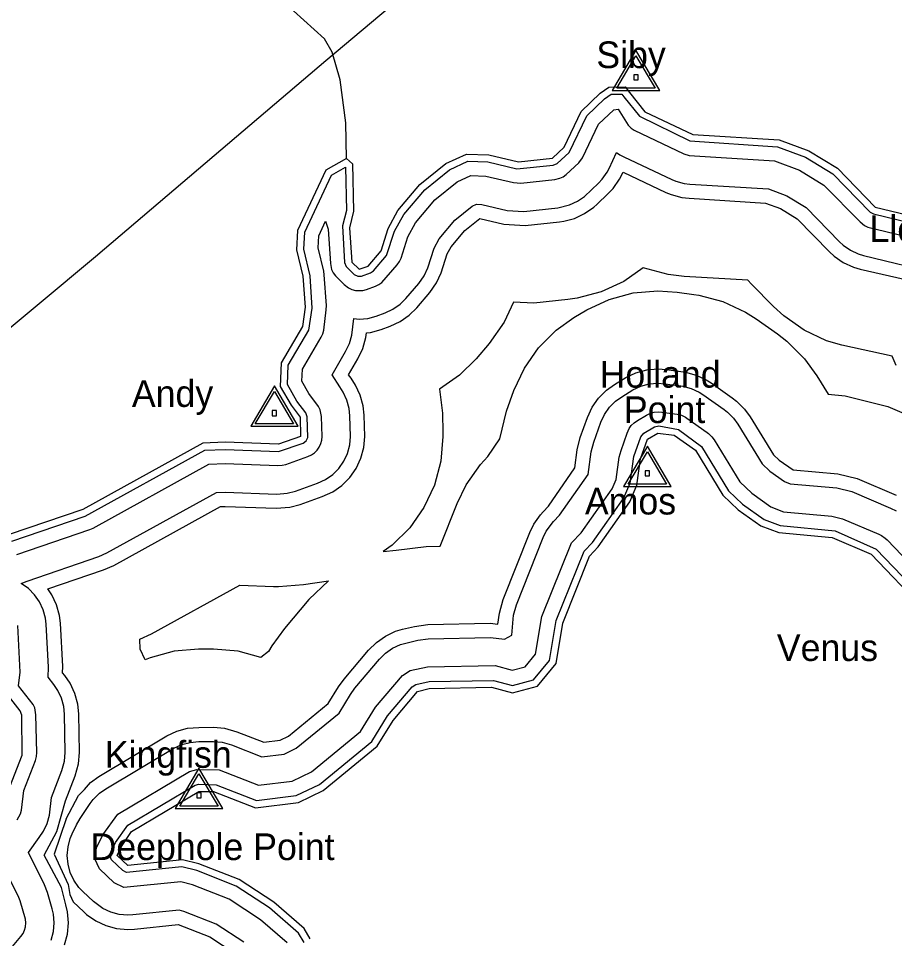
# Model space of a CAD drawing. Extents: x 2532689 to 2764727, y 536648 to 732970.
# Drawn here: x 2659104 to 2664029, y 576983 to 582158 of the extents above; entities that cross this region are included whole.
import ezdxf

# ---------------------------------------------------------------- set-up
doc = ezdxf.new("R2010")
doc.units = 0
for name, color, linetype in [('Exist Hydrographic Buffer Line', 7, 'Continuous'), ('Exist Hydrographic Creek Double Shore', 7, 'Continuous'), ('Exist Hydrographic Creek Single Shore', 7, 'Continuous'), ('Exist Hydrographic Point Label', 7, 'Continuous'), ('Exist Railroad Mainline', 7, 'Continuous'), ('Exist Survey Geodetic Marker CELL', 7, 'Continuous'), ('Exist Survey Geodetic Marker Label', 7, 'Continuous')]:
    doc.layers.add(name, color=color, linetype=linetype)

msp = doc.modelspace()

# ---------------------------------------------------------------- linework, layer by layer
at = {"layer": 'Exist Hydrographic Buffer Line'}
for points in [[(2661033.1, 580709.3), (2661083.1, 580727.7), (2661099.5, 580739.2), (2661172.5, 580824.2), (2661218.2, 580960.8), (2661270.5, 581054.6), (2661387.6, 581194.8), (2661527.4, 581306.8), (2661630.4, 581354.7), (2661741.7, 581350.4), (2661905.2, 581312.1), (2662110.6, 581332.1), (2662132.1, 581341.2), (2662198.8, 581404.6), (2662299.3, 581610.8), (2662398.9, 581706.4), (2662435, 581732.2), (2662494.9, 581732.5), (2662507.8, 581716), (2662594.1, 581607.7), (2662878.3, 581469.3), (2663370.9, 581436.3), (2663529, 581377.6), (2663682.1, 581283.6), (2663891.9, 581069.2), (2663911, 581058.3), (2664359, 580949.8)], [(2660699.9, 580185.2), (2660804.8, 580364.7), (2660814.1, 580384.3), (2660819.6, 580404.5), (2660834.4, 580519), (2660835, 580542.5), (2660823.1, 580716.1), (2660820, 580735.8), (2660788, 580868.3), (2660791.7, 580936), (2660830.3, 581018.1), (2660844.6, 580972.9), (2660857.5, 580779.7), (2660864.5, 580746.7), (2660873.3, 580727.8), (2660885.2, 580710.7), (2660935.5, 580660.9), (2660959.2, 580642.9), (2660978.3, 580634.1), (2660998.6, 580628.7), (2661019.3, 580626.9), (2661040, 580628.7), (2661060.3, 580634.1), (2661110.8, 580652.6), (2661129.2, 580661.3), (2661146.5, 580673.3), (2661233.2, 580772.2), (2661246.3, 580790.3), (2661255.1, 580809.3), (2661292.2, 580929.3), (2661336.7, 581009.2), (2661443.8, 581137.3), (2661570.1, 581238.3), (2661646.6, 581274), (2661731.1, 581270.8), (2661886.9, 581234.2), (2661927.3, 581231.7), (2662119.2, 581252.5), (2662147.3, 581259.1), (2662166.4, 581267.9), (2662183.6, 581279.9), (2662254.1, 581346.6), (2662275.3, 581373.6), (2662365.3, 581563.2), (2662450, 581644.5), (2662474.8, 581647.6), (2662531.4, 581557.9), (2662548, 581540.6), (2662565.4, 581528.6), (2662844.3, 581396.9), (2662874.6, 581387.3), (2663354, 581357.2), (2663493.7, 581305.3), (2663631.9, 581220.5), (2663834.7, 581013.3), (2663860.3, 580993.2), (2663879.4, 580984.4), (2664329.7, 580874.5)], [(2660966, 579759), (2660970.3, 579807.6), (2660967.2, 579923.7), (2660963.1, 579964.5), (2660950.2, 580011.7), (2660929.7, 580055.9), (2660910, 580085.7), (2660866.6, 580153.1), (2660943, 580284), (2660964.4, 580329.6), (2660977.1, 580376.8), (2660989.4, 580469.5), (2661019.3, 580466.9), (2661067.7, 580471.1), (2661115.1, 580483.7), (2661165.7, 580502.4), (2661209.2, 580522.7), (2661249.4, 580550.7), (2661281.8, 580582.9), (2661354.8, 580667.9), (2661384.7, 580710.3), (2661405.2, 580754.6), (2661440.3, 580866.1), (2661469.2, 580918.2), (2661556.4, 581022.5), (2661654.8, 581101.4), (2661679, 581112.6), (2661709.5, 581111.5), (2661850.4, 581078.4), (2661944.5, 581072.6), (2662136.7, 581093.5), (2662202.1, 581108.7), (2662246.4, 581129.3), (2662286.3, 581157.3), (2662364.1, 581230.6), (2662385.8, 581253.6), (2662413.9, 581293.6), (2662424.3, 581313.9), (2662466.6, 581403.2), (2662485.2, 581390.1), (2662506.2, 581379.2), (2662776, 581252.1), (2662799.6, 581242.4), (2662846.7, 581229.8), (2662878.1, 581226), (2663320.6, 581198.9), (2663423.4, 581160.7), (2663531.4, 581094.5), (2663720.1, 580901.5), (2663740.4, 580882.7), (2663780.4, 580854.7), (2663824.6, 580834.1), (2663854.4, 580825), (2664271.7, 580724)], [(2659066.4, 579218.2), (2659478.4, 579359.2), (2660151.3, 579729.5), (2660265.3, 579734.1), (2660564.7, 579723.2), (2660703.8, 579769.9), (2660721, 579781.9), (2660729.8, 579800.7), (2660727.3, 579917), (2660719.1, 579940.1), (2660669.5, 580005), (2660615.8, 580098.5), (2660620.7, 580208.5), (2660735.7, 580405.2), (2660755, 580529.2), (2660743.3, 580710.5), (2660707.4, 580861), (2660712.8, 580956), (2660863.3, 581275.6), (2660941.8, 581321.5), (2660947.4, 581078.3), (2660925.6, 580990.6), (2660937.3, 580785.1), (2660946.5, 580762.1), (2660991.2, 580718.2), (2661012.4, 580707.5), (2661033.1, 580709.3)], [(2659292, 578917.1), (2659269.4, 578949.3), (2659582.1, 579056.4), (2659639.1, 579081.6), (2660239.7, 579412.8), (2660266, 579413.8), (2660553.2, 579403.5), (2660628.7, 579408.7), (2660687.6, 579424.3), (2660811.6, 579468.7), (2660870.3, 579495.8), (2660921.7, 579531.8), (2660966, 579576.2), (2661002.1, 579627.6), (2661028.6, 579684.5), (2661044.8, 579745.1), (2661050.3, 579807.6), (2661047, 579925.8), (2661041.9, 579978.4), (2661025.5, 580039), (2660999, 580095.9), (2660973.6, 580134.2), (2660959, 580153.1), (2661012.1, 580243.6), (2661039.6, 580302.2), (2661055.8, 580362.9), (2661059.7, 580390.4), (2661081.9, 580392.4), (2661142.6, 580408.5), (2661193.6, 580427.3), (2661249.4, 580453.5), (2661300.9, 580489.5), (2661342.5, 580530.8), (2661415.5, 580615.9), (2661454, 580670.3), (2661480.5, 580727.2), (2661514.3, 580834.6), (2661535.6, 580872.8), (2661612.5, 580965), (2661697, 581032.2), (2661832.2, 581000.5), (2661953.1, 580993.1), (2662145.1, 581014), (2662168.8, 581017.3), (2662229.5, 581033.5), (2662286.3, 581060.1), (2662337.8, 581096.1), (2662354.4, 581110.8), (2662419.4, 581172.6), (2662447.1, 581202.2), (2662483, 581253.6), (2662502.9, 581292.4), (2662742.2, 581179.7), (2662772.1, 581167.2), (2662832.8, 581151), (2662873.4, 581146.2), (2663303.8, 581119.8), (2663388.1, 581088.5), (2663481.2, 581031.5), (2663662.9, 580845.6), (2663688.9, 580821.4), (2663740.4, 580785.4), (2663797.2, 580758.9), (2663835.7, 580747.3), (2664246.8, 580654.7)], [(2664037.1, 580206.3), (2664016.2, 580258.1), (2663732, 580319.6), (2663646.9, 580345.4), (2663520.3, 580404.3), (2663406.1, 580484.4), (2663348.1, 580538), (2663224.7, 580664.3), (2663204.4, 580685.1), (2662846.3, 580707), (2662756.3, 580717.6), (2662616.3, 580756), (2662506.4, 580679), (2662379.8, 580620.1), (2662245.3, 580584), (2662192.6, 580576.5), (2662000.5, 580555.7), (2661887.5, 580562.6), (2661835, 580450.3), (2661749.3, 580329.3), (2661676.3, 580244.3), (2661583.6, 580152.4), (2661470.2, 580073.1), (2661487, 579938), (2661490.1, 579829.8), (2661490.3, 579807.6), (2661478, 579668.7), (2661442.1, 579534), (2661383.1, 579407.6), (2661303.1, 579293.4), (2661204.5, 579194.8), (2661154.7, 579159.9), (2661226.8, 579166.8), (2661396, 579188.7), (2661474.5, 579190.4), (2661570.1, 579430.1), (2661620.5, 579534.4), (2661700.5, 579648.7), (2661742.5, 579695.1), (2661809.2, 579793.1), (2661847.3, 579948.9), (2661888.5, 580064.8), (2661947.6, 580191.1), (2662027.6, 580305.4), (2662126, 580404), (2662225.4, 580475.2), (2662298.4, 580519.2), (2662424.8, 580578.1), (2662559.3, 580614.3), (2662698.3, 580626.4), (2662807.6, 580618.9), (2662899.7, 580606.2), (2662929.4, 580601.6), (2663063.9, 580565.5), (2663190.4, 580506.5), (2663251.3, 580467.6)], [(2663251.3, 580467.6), (2663370.5, 580383.7), (2663423.6, 580342.7), (2663522.2, 580244.1), (2663591.7, 580147.6), (2663654.9, 580044.3), (2663750.6, 580035.6), (2663991.1, 579975.3), (2664210.1, 579882.3)], [(2659371.6, 577657.6), (2659441, 577787.3), (2659474.6, 577821.2), (2659507.9, 577861.5), (2659555, 577895), (2659937.3, 578122.9), (2659994.1, 578149.5), (2660054.8, 578165.7), (2660116.9, 578171.2), (2660200.3, 578171.3), (2660262.9, 578165.8), (2660331.6, 578146.6), (2660482.9, 578087.4), (2660574.2, 578098.5), (2660621.9, 578121.7), (2660845.4, 578305.1), (2660902.7, 578398.4), (2660934.4, 578442.3), (2661072.4, 578605.5), (2661115.9, 578648.8), (2661167.4, 578684.8), (2661224.2, 578711.4), (2661263.3, 578723.1), (2661329.4, 578738.9), (2661405.6, 578748.8), (2661755.7, 578756.4), (2661797.9, 578751.3), (2661808, 578813.5), (2661828.9, 578890.4), (2661978.8, 579267.5), (2662001.5, 579314.5), (2662037.6, 579365.8), (2662053.4, 579383.4), (2662083.3, 579414.9), (2662230.6, 579630.3), (2662244.9, 579731.7), (2662262.1, 579801.7), (2662302.1, 579914.3), (2662328.6, 579971.2), (2662364.7, 580022.5), (2662408.8, 580066.9), (2662453.7, 580099), (2662518.5, 580138.1), (2662575.1, 580164.7), (2662636, 580180.9), (2662698.3, 580186.4), (2662747.7, 580183), (2662852.9, 580168.2), (2662913.6, 580152), (2662970.4, 580125.5), (2662997.9, 580107.9), (2663116.8, 580024.1), (2663140.8, 580005.6), (2663185.1, 579961.2), (2663216.5, 579917.8), (2663347.5, 579704), (2663379.7, 579672.8), (2663459.4, 579620.2), (2663710.8, 579597.4), (2663819.1, 579570.2), (2664038.1, 579477.2)], [(2660800.1, 579957), (2660791.3, 579975.9), (2660736.4, 580049.4), (2660696.8, 580118.2), (2660699.9, 580185.2)], [(2662306.1, 579592.8), (2662324.1, 579720.5), (2662337.6, 579775), (2662377.4, 579886.9), (2662397.9, 579931.2), (2662425.8, 579971.2), (2662460.4, 580005.7), (2662495.1, 580030.6), (2662558.4, 580068.9), (2662602.5, 580089.5), (2662649.9, 580102.1), (2662698.3, 580106.4), (2662736.6, 580103.7), (2662839, 580089.4), (2662886.1, 580076.8), (2662930.4, 580056.2), (2662951.5, 580042.6), (2663070.7, 579958.7), (2663089.3, 579944.3), (2663124, 579909.8), (2663148.2, 579876.1), (2663284.3, 579653.5), (2663328.6, 579611), (2663409.4, 579553.6), (2663441.2, 579541.5), (2663703.7, 579517.7), (2663787.9, 579496.6), (2664006.9, 579403.6), (2664037.5, 579388.3)], [(2659095.3, 579143.4), (2659504.2, 579283.5), (2659523.3, 579291.9), (2660173.5, 579650.3), (2660265.6, 579654), (2660562.1, 579643.3), (2660587.1, 579645), (2660606.8, 579650.2), (2660730.8, 579694.6), (2660750.3, 579703.7), (2660767.5, 579715.7), (2660782.3, 579730.5), (2660794.4, 579747.6), (2660803, 579766.5), (2660808.5, 579786.8), (2660810.4, 579807.6), (2660807.3, 579919.2), (2660800.1, 579957)], [(2662441.4, 579512.8), (2662463.8, 579564.9), (2662481.4, 579689.9), (2662491.1, 579728.8), (2662525.7, 579826.3), (2662537.2, 579851.1), (2662548.9, 579867.8), (2662564.3, 579883.2), (2662583.3, 579896.9), (2662633.9, 579927.5), (2662657.5, 579938.5), (2662677.8, 579943.9), (2662699.8, 579945.8), (2662720, 579944.4), (2662807.1, 579932.2), (2662831.3, 579925.8), (2662852.9, 579915.7), (2662862, 579909.8), (2662975.8, 579829.8), (2662983.6, 579823.7), (2663001.6, 579805.8), (2663014.7, 579787.6), (2663158.6, 579552.3), (2663226.3, 579487.3), (2663333.4, 579411.2), (2663404.8, 579384), (2663676.8, 579359.4), (2663736.9, 579344.4), (2663939.8, 579258.2), (2663955.4, 579250.5), (2663976.4, 579235.7), (2663987.4, 579225.4), (2664271.5, 578928.1)], [(2662505.1, 579458.7), (2662541.6, 579543.5), (2662563.6, 579694.7), (2662602.9, 579804.9), (2662619.6, 579825.4), (2662678.4, 579861), (2662703.8, 579866), (2662813.3, 579846.4), (2662943.3, 579750.7), (2663095.9, 579501.9), (2663174.8, 579425.6), (2663295.4, 579340.3), (2663386.4, 579305.4), (2663694.2, 579275.7), (2663926.3, 579173.5), (2664219, 578867.2)], [(2659288.3, 576975.2), (2659301, 577022.4), (2659305.3, 577071), (2659301, 577119.7), (2659293.8, 577150.8), (2659266.7, 577241.7), (2659249.3, 577286), (2659160.1, 577466.7), (2659221, 577551.9), (2659244.8, 577586.8), (2659265.3, 577631), (2659278, 577678.2), (2659290.3, 577777.5), (2659348.4, 577927.9), (2659363.1, 577980.4), (2659367.2, 578029), (2659362.3, 578245.6), (2659358, 578287.6), (2659345.3, 578334.7), (2659324.8, 578379), (2659302, 578412.5), (2659270.2, 578452.6), (2659272.7, 578509.7), (2659259.8, 578752.2), (2659256.1, 578785.8), (2659243.2, 578832.9), (2659222.7, 578877.2), (2659194.8, 578917.1), (2659160.3, 578951.6), (2659119.7, 578979.9), (2659152.5, 578993.9), (2659556.1, 579132.1), (2659600.6, 579151.7), (2660217.6, 579491.9), (2660265.8, 579493.9), (2660556.3, 579483.4), (2660614.8, 579487.4), (2660660.5, 579499.6), (2660784.5, 579544), (2660830.3, 579565.1), (2660870.3, 579593.1), (2660904.9, 579627.6), (2660932.8, 579667.6), (2660953.3, 579711.9), (2660966, 579759)], [(2660370.3, 576964), (2660216.1, 577064.7), (2660033.8, 577136.5), (2660006.4, 577143.1), (2659747.6, 577116), (2659718.3, 577114.5), (2659669.9, 577118.7), (2659622.5, 577131.3), (2659578.2, 577151.9), (2659525.7, 577191), (2659465.9, 577247.8), (2659443.9, 577271.2), (2659415.8, 577311.2), (2659395.3, 577355.5), (2659382.6, 577402.6), (2659378.3, 577451.2), (2659382.6, 577499.8), (2659395.3, 577547), (2659405.8, 577572), (2659429.8, 577622.2), (2659450.3, 577658.2), (2659507.3, 577742.5), (2659524.7, 577765.8), (2659559.4, 577800.3), (2659595.9, 577826.3), (2659977.3, 578053.7), (2660021.5, 578074.3), (2660068.9, 578086.9), (2660116.9, 578091.2), (2660200.3, 578091.3), (2660248.7, 578087.1), (2660302.3, 578072.1), (2660472.7, 578005.5), (2660597.1, 578020.7), (2660665.4, 578053.9), (2660906.3, 578251.8), (2660970.9, 578356.5), (2660995.5, 578390.7), (2661133.5, 578553.8), (2661167.4, 578587.6), (2661207.4, 578615.6), (2661251.6, 578636.2), (2661282, 578645.3), (2661348, 578661.2), (2661407.3, 578668.8), (2661757.3, 578676.4), (2661835.8, 578666.9), (2661877.4, 578688.9), (2661886.9, 578801.1), (2661903.1, 578860.9), (2662053.2, 579237.9), (2662070.8, 579274.4), (2662111, 579328.1), (2662145.3, 579363.9), (2662306.1, 579592.8)], [(2660613.9, 576960), (2660464.8, 577089.4), (2660288.4, 577204.6), (2660081.3, 577286.2), (2660016.8, 577301.8), (2659695.5, 577269.8), (2659642.3, 577296.5), (2659558.9, 577376), (2659532.8, 577431.5), (2659541.7, 577493.1), (2659577.2, 577566.7), (2659661.5, 577683), (2660064.6, 577923.2), (2660107.3, 577934.8), (2660231.7, 577931.4), (2660452.3, 577845.2), (2660641.9, 577868.4), (2660750.4, 577921), (2661026.3, 578147.4), (2661111.3, 578284.7), (2661261.9, 578462.9), (2661306.3, 578490.1), (2661402.6, 578512), (2661784, 578518.6), (2661880.1, 578492.8), (2661951.9, 578512.4), (2662011.1, 578582.7), (2662045.5, 578794.8), (2662213.1, 579208.4), (2662267, 579264.3), (2662441.4, 579512.8)], [(2660710.1, 576962.1), (2660678.3, 577014.4), (2660515.1, 577156), (2660326.9, 577279), (2660106.4, 577365.9), (2660022.6, 577386.1), (2659711.3, 577355.1), (2659690.8, 577365.4), (2659627.6, 577425.5), (2659618.8, 577444.3), (2659622.3, 577468.5), (2659649, 577523.8), (2659718.9, 577620.2), (2660097.4, 577845.8), (2660117.3, 577851.2), (2660214.9, 577848.6), (2660441.5, 577759.9), (2660665.8, 577787.4), (2660795.6, 577850.4), (2661089.9, 578091.8), (2661178.9, 578235.6), (2661316.9, 578398.9), (2661338.2, 578411.9), (2661412.6, 578428.9), (2661773.7, 578435.1), (2661880.3, 578406.5), (2661998.9, 578438.9), (2662089.7, 578546.6), (2662126.2, 578772.2), (2662284.3, 579162.2), (2662331.5, 579211.2), (2662505.1, 579458.7)], [(2659816.5, 578550.2), (2659788.2, 578610.8), (2659785.3, 578667), (2659851.6, 578696.3), (2660348.8, 578970.5), (2660537.2, 578963.7), (2660566.4, 578963.2), (2660705.4, 578975.3), (2660846.3, 578995.1), (2660736.6, 578889.6), (2660598.6, 578726.4), (2660527.8, 578628.8), (2660509.2, 578598.4), (2660466.5, 578563.5), (2660339.4, 578599.2), (2660200.3, 578611.3), (2660116.1, 578611.2), (2659978.3, 578599.1), (2659843.8, 578562.9), (2659816.5, 578550.2)], [(2659368.5, 577757.9), (2659368.5, 577758.1), (2659423, 577899), (2659441.9, 577966.5), (2659447.2, 578029), (2659442.3, 578247.5), (2659436.7, 578301.5), (2659420.5, 578362.1), (2659394.1, 578419), (2659364.8, 578462.1), (2659351.8, 578478.6), (2659352.9, 578514), (2659339.7, 578756.4), (2659334.8, 578799.6), (2659318.4, 578860.3), (2659292, 578917.1)], [(2659095.9, 577651.8), (2659115, 577685.7), (2659120.5, 577705.9), (2659133.9, 577816.4), (2659199.3, 577985.6), (2659205.4, 578008.1), (2659207.3, 578029), (2659202.4, 578241.9), (2659195, 578280), (2659186.4, 578299), (2659103.9, 578405.1), (2659112.5, 578481.4), (2659100, 578743.6)], [(2659055.5, 577835.8), (2659124.4, 578014.5), (2659122.2, 578239.9), (2659113.8, 578263.7), (2659020.7, 578381.3)], [(2659363.5, 576947.9), (2659379.7, 577008.5), (2659385.3, 577071), (2659379.7, 577133.5), (2659370.3, 577173.5), (2659346.5, 577271.2), (2659247.4, 577451.5), (2659320.1, 577584.8), (2659368.5, 577758.1)], [(2659371.6, 577657.6), (2659305, 577457.6), (2659383.7, 577287.9), (2659392.8, 577230.3), (2659410.9, 577189.6), (2659470.8, 577132.9), (2659486.8, 577118.7), (2659538.2, 577082.7), (2659595, 577056.1), (2659655.7, 577040), (2659718.3, 577034.5), (2659755.8, 577036.4), (2660001, 577062.1), (2660179.4, 576993.2), (2660321.9, 576900)], [(2659052.3, 576915.8), (2659117.5, 576994.3), (2659129.4, 577011), (2659138, 577029.9), (2659143.5, 577050.2), (2659145.4, 577071), (2659143.5, 577091.8), (2659113.4, 577196.1), (2659105.8, 577215.1), (2659007.6, 577413.9)]]:
    msp.add_lwpolyline(points, dxfattribs=at)
at = {"layer": 'Exist Hydrographic Creek Double Shore'}
for points in [[(2661019.3, 580746.9), (2661069.4, 580765.2), (2661142.4, 580850.3), (2661181.3, 580976.6), (2661237.3, 581077.4), (2661359.3, 581223.5), (2661506.3, 581341.1), (2661622.4, 581395), (2661747.3, 581390.2), (2661914.4, 581351), (2662106.3, 581371.9), (2662171.3, 581433.6), (2662266.2, 581634.5), (2662373.3, 581737.2), (2662422.3, 581772.1), (2662514.4, 581772.5), (2662539.4, 581740.7), (2662625.3, 581632.5), (2662895.3, 581505.5), (2663379.3, 581475.8), (2663546.4, 581413.6), (2663707.4, 581315.1), (2663920.4, 581097.2), (2664373.4, 580987.4)], [(2660947.4, 581371), (2660832.3, 581304), (2660673.2, 580966), (2660667.3, 580857.3), (2660703.3, 580707.8), (2660715.2, 580534.3), (2660701.3, 580425.3), (2660581.3, 580220.2), (2660575.2, 580088.7), (2660636.3, 579982.8), (2660687.3, 579915.9), (2660690.2, 579807.6)], [(2660947.4, 581371), (2660981.2, 581339.6), (2660987.3, 581073.9), (2660964.4, 580981), (2660977.3, 580787.8), (2661019.3, 580746.9)], [(2659658.4, 577451.2), (2659682.4, 577501.4), (2659739.4, 577585.8), (2660117.3, 577811.2), (2660200.3, 577811.3), (2660436.4, 577719), (2660677.3, 577748.4), (2660817.3, 577816.5), (2661120.4, 578065.1), (2661209.4, 578209.9), (2661347.4, 578373), (2661413.4, 578388.9), (2661763.5, 578396.5), (2661880.3, 578365.1), (2662021.4, 578403.6), (2662127.4, 578529.3), (2662163.3, 578757.4), (2662313.4, 579134.5), (2662362.4, 579185.7), (2662540.4, 579439.1), (2662580.4, 579532.6), (2662601.3, 579681.3), (2662640.5, 579791.2), (2662698.3, 579826.4), (2662790.4, 579813.7), (2662909.3, 579729.8), (2663064.3, 579476.7), (2663149.4, 579394.8), (2663276.3, 579304.7), (2663377.4, 579266.1), (2663678.4, 579238.9), (2663897.4, 579145.9), (2664187.4, 578842.3)], [(2660690.2, 579807.6), (2660566.4, 579763.2), (2660265.3, 579774.1), (2660140.3, 579769), (2659465.2, 579397), (2659052.3, 579255.5), (2658972.1, 579221.4)], [(2660744.4, 576982.8), (2660709.3, 577040.5), (2660539.3, 577188), (2660345.3, 577314.8), (2660118.3, 577404.1), (2660025.2, 577426.6), (2659718.3, 577394.5), (2659658.4, 577451.2)]]:
    msp.add_lwpolyline(points, dxfattribs=at)
at = {"layer": 'Exist Hydrographic Creek Single Shore'}
msp.add_lwpolyline([(2660947.4, 581371), (2660943.3, 581571.2), (2660912.3, 581812.9), (2660867.2, 581968.7), (2660824.3, 582042.4), (2660475.3, 582360), (2660277.2, 582624.5), (2660191.1, 582778.6), (2660140.3, 582829.1)], dxfattribs=at)
at = {"layer": 'Exist Railroad Mainline'}
msp.add_lwpolyline([(2657243.3, 576807.6), (2657246.9, 577287.8), (2657249.3, 577707.8), (2657257.8, 577872.3), (2657292, 578049), (2657340.2, 578222), (2657404.9, 578367.5), (2657483.9, 578509.2), (2657617.7, 578782.2), (2657771.4, 579073.7), (2658014.6, 579395.2), (2658195.8, 579607.4), (2658478.9, 579913.6), (2658891, 580280.6), (2659537.4, 580819.3), (2660116.4, 581312.2), (2660831.2, 581921.9), (2661345.7, 582353.4)], dxfattribs=at)
at = {"layer": 'Exist Survey Geodetic Marker CELL'}
for points in [[(2662709, 581753.1), (2662575, 581979.2), (2662441.5, 581753.1)], [(2662683, 581765.2), (2662467.5, 581765.2), (2662575, 581947.4)], [(2662587.3, 581811.8), (2662587.3, 581840.1), (2662563.1, 581840.1), (2662563.1, 581811.8)], [(2660676.6, 579865.2), (2660542.7, 580091.2), (2660409.2, 579865.2)], [(2660650.7, 579877.3), (2660435.2, 579877.3), (2660542.7, 580059.4)], [(2660555, 579923.9), (2660555, 579952.1), (2660530.7, 579952.1), (2660530.7, 579923.9)], [(2662773.3, 579526.2), (2662639.3, 579752.2), (2662505.8, 579526.2)], [(2662747.4, 579538.3), (2662531.8, 579538.3), (2662639.3, 579720.5)], [(2662651.6, 579584.9), (2662651.6, 579613.2), (2662627.4, 579613.2), (2662627.4, 579584.9)], [(2660252.2, 577715.5), (2660118.2, 577941.5), (2659984.7, 577715.5)], [(2660226.2, 577727.6), (2660010.7, 577727.6), (2660118.2, 577909.8)], [(2660130.5, 577774.2), (2660130.5, 577802.5), (2660106.3, 577802.5), (2660106.3, 577774.2)]]:
    msp.add_lwpolyline(points, close=True, dxfattribs=at)

# ---------------------------------------------------------------- texts
at = {"layer": 'Exist Hydrographic Point Label'}
for s, p in [('Holland', (2662370.6, 580081.7)), ('Point', (2662507.2, 579882.5)), ('Deephole Point', (2659508.9, 577424.8))]:
    msp.add_text(s, height=150, dxfattribs=at).set_placement(p)
at = {"layer": 'Exist Survey Geodetic Marker Label'}
for s, p in [('Siby', (2662352.4, 581878.3)), ('Llewwllyn', (2663888, 580900)), ('Andy', (2659741.3, 579973.2)), ('Amos', (2662288.1, 579368.2)), ('Venus', (2663367, 578544.4)), ('Kingfish', (2659589.1, 577943.7))]:
    msp.add_text(s, height=150, dxfattribs=at).set_placement(p)

doc.saveas('drawing.dxf')
